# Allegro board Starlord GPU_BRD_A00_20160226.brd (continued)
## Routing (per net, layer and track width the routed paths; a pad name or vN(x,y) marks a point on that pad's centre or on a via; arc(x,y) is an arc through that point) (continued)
FBA_CMD27: length 37.3
  TOP w0.114: v1(33.92,67.36) 33.92,66.9 v2(34.02,66.8) ; v2(21.45,85.27) 21.53,85.27 VRAM3.H5
  L3 w0.127: v2(21.45,85.27) 20.92,85.81 20.92,88.55 20.77,88.7 20.28,88.7 20.14,88.55 20.14,78.59 23.37,75.35 23.37,74.47 26.39,71.45 30.41,71.45 31.4,70.47 31.69,70.47 32.11,70.06 32.11,68.98 32.92,68.17 32.95,68.16 33.23,68.16 33.82,67.57 33.82,67 v2(34.02,66.8)
  BOTTOM w0.114: VRAM3.H5 21.53,85.27 v2(21.45,85.27) ; v2(34.02,66.8) GPU1.J24
FBA_CMD28: length 36.3
  TOP w0.114: v2(24,83.6) 24,83.6 23.61,84 VRAM3.G3
  L3 w0.127: v2(32.48,72.14) 32.48,72.18 27.75,76.9 27.75,80.98 27.42,81.31 26.42,81.31 26.25,81.47 26.25,81.8 26.42,81.97 28.2,81.97 28.36,82.13 28.36,82.46 28.2,82.63 26.42,82.63 26.25,82.79 26.25,83.12 26.42,83.29 28.2,83.29 28.36,83.45 28.36,83.78 28.2,83.95 26.42,83.95 26.25,84.11 26.25,84.44 26.42,84.61 28.2,84.61 28.36,84.77 28.36,85.12 28.22,85.27 25.78,85.27 25.25,84.74 25.25,83.86 24.99,83.6 v2(24,83.6)
  BOTTOM w0.114: GPU1.K27 33.62,69.62 33.5,69.74 33.5,70.9 32.48,71.92 v2(32.48,72.14) ; VRAM3.G3 v2(24,83.6)
FBA_CMD29: length 39.4
  TOP w0.114: v2(23.99,85.99) 24.38,85.6 VRAM3.J2
  L3 w0.127: v2(34.1,72.19) 34.1,72.35 29.62,76.84 29.62,89.82 29.32,90.12 27.36,90.12 27.2,90.28 27.2,91.89 27.03,92.05 26.7,92.05 26.54,91.89 26.54,90.28 26.37,90.12 25.08,90.12 24.86,89.89 24.86,87.76 24.5,87.4 24.5,86.51 v2(23.99,85.99)
  BOTTOM w0.114: VRAM3.J2 24.38,85.6 v2(23.99,85.99) ; R7521.2 34.14,72.15 v2(34.1,72.19) 34.1,72.09 33.74,71.73 33.74,69.84 33.97,69.61 33.97,67.84 33.62,67.49 GPU1.K25
FBA_CMD30: length 43.3
  TOP w0.114: R7524.1 v1(27.63,85.86) 26.46,85.86 25.8,85.19 v2(23.99,85.19) 23.99,85.21 VRAM3.J3
  L3 w0.127: v2(34.15,71.45) 33.36,72.25 33.36,72.51 29.2,76.66 29.2,89.36 29.07,89.49 28.67,89.49 28.54,89.36 28.54,87.95 28.41,87.82 28.01,87.82 27.88,87.95 27.88,89.31 27.75,89.44 27.35,89.44 27.22,89.31 27.22,87.95 27.09,87.82 26.56,87.82 26.39,87.99 26.39,89.07 26.22,89.24 25.45,89.24 25.24,89.03 25.24,85.82 24.97,85.55 24.35,85.55 v2(23.99,85.19)
  BOTTOM w0.114: GPU1.J27 34.42,69.5 33.98,69.94 33.98,71.28 v2(34.15,71.45) ; VRAM3.J3 23.99,85.21 v2(23.99,85.19)
FBA_CMD31: length 38.9
  TOP w0.114: v2(23.2,86.8) 23.2,86.8 VRAM3.L3
  L3 w0.127: v2(23.2,86.8) 23.2,87.5 23.49,87.79 24.32,87.79 24.45,87.91 24.45,92.18 24.81,92.54 27.82,92.54 30.04,90.33 30.04,77.01 34.59,72.46 34.59,71.24 34.55,71.19 v2(34.55,70.84)
  BOTTOM w0.114: v2(34.55,70.84) 34.22,70.51 34.22,70.04 34.68,69.58 34.68,69.03 34.77,68.94 34.77,68.66 34.42,68.31 GPU1.J26 ; VRAM3.L3 23.6,87.2 v2(23.2,86.8)
FBA_D0: length 24.9
  L6 w0.127: v2(39.64,78.74) 39.64,77.97 44.08,73.53 44.08,65.33 42.23,63.48 41.47,63.48 39.51,61.52 38.01,61.52 37.49,60.99 v2(37.42,60.99)
  BOTTOM w0.114: GPU1.E18 37.43,61.05 37.43,61 v2(37.42,60.99) ; v2(39.64,78.74) 39.64,78.76 VRAM1.A4
FBA_D1: length 25.8
  L6 w0.127: v2(36.57,60.99) 36.59,60.99 37.44,61.84 39.39,61.84 41.35,63.8 41.78,63.8 43.73,65.74 43.73,73.13 v2(38.78,78.08)
  BOTTOM w0.114: GPU1.F18 36.59,61.05 36.59,61.01 v2(36.57,60.99) ; VRAM1.A2 37.6,79.11 38.63,78.08 v2(38.78,78.08)
FBA_D2: length 28.5
  TOP w0.114: v2(37.38,59.34) 36.99,59.72 v1(36.99,59.77)
  L6 w0.127: v2(37.38,59.34) 37.49,59.45 39.45,59.45 44.8,64.79 44.8,74.54 39.92,79.42 39.78,79.42 v2(39.6,79.6)
  BOTTOM w0.114: v2(39.6,79.6) VRAM1.B4 ; GPU1.E16 37.79,59.74 37.38,59.34 v2(37.38,59.34)
FBA_D3: length 30.2
  L6 w0.127: v2(36.57,60.18) 36.99,59.76 37.83,59.76 37.88,59.71 39.18,59.71 44.44,64.98 44.44,73.76 40.19,78.01 40.19,78.79 39.81,79.16 39.25,79.16 v2(38.8,78.72)
  BOTTOM w0.114: v2(36.57,60.18) 36.96,60.57 GPU1.F17 ; v2(38.8,78.72) 38.33,78.72 37.99,79.06 37.99,79.61 VRAM1.B2
FBA_D4: length 27.8
  TOP w0.114: v2(39,63.45) 39.48,63.45 v1(39.55,63.38)
  L6 w0.127: v2(39,63.45) 39.49,63.45 40.9,64.86 41.37,64.86 42.55,66.04 42.55,70.79 39.08,74.26 39.08,75.2 36.81,77.47 36.81,81.01 36.78,81.04 36.78,81.39 38.61,83.22 38.97,83.22 39.39,82.81 v2(39.6,82.81)
  BOTTOM w0.114: VRAM1.E4 39.2,82.4 v2(39.6,82.81) ; GPU1.D20 38.99,63.45 v2(39,63.45)
FBA_D5: length 26.5
  L6 w0.127: v2(37.2,82.81) 36.73,82.81 36.44,83.1 36.09,83.1 35.82,82.83 35.82,77.65 38.54,74.92 38.54,69.85 41.44,66.95 41.44,65.54 41.17,65.26 40.75,65.26 39.36,63.87 38.61,63.87 v2(38.19,63.46)
  BOTTOM w0.114: v2(38.19,63.46) 38.19,63.5 GPU1.D21 ; VRAM1.E2 37.2,82.8 v2(37.2,82.81)
FBA_D6: length 31.5
  TOP w0.114: v1(36.55,62.03) 36.55,62.65 v2(36.55,62.66)
  L6 w0.127: v2(39.6,83.61) 39.35,83.85 36.6,83.85 36.44,84.01 36.09,84.01 35.11,83.03 35.11,76.98 37.4,74.69 37.4,69.93 40.23,67.1 40.23,65.74 39.18,64.69 38.36,64.69 37.57,63.9 37.21,63.9 36.92,63.61 36.92,63.02 v2(36.55,62.66)
  BOTTOM w0.114: VRAM1.F4 39.2,83.21 v2(39.6,83.61) ; v2(36.55,62.66) 36.56,62.66 GPU1.F20
FBA_D7: length 27.4
  TOP w0.114: v1(36.74,63.3) 37.2,63.3 v2(37.38,63.48)
  L6 w0.127: v2(37.38,63.48) 37.51,63.48 38.16,64.12 39.11,64.12 40.58,65.6 40.58,67.3 37.97,69.91 37.97,74.83 35.46,77.34 35.46,82.83 36.22,83.59 v2(36.26,83.59)
  BOTTOM w0.114: VRAM1.F2 37.21,83.59 v2(36.26,83.59) ; GPU1.E21 37.42,63.52 v2(37.38,63.48)
FBA_D8: length 29.8
  TOP w0.114: VRAM2.U11 44.38,78.78 v2(44.38,78.74)
  L6 w0.127: v2(38.18,58.51) 38.38,58.51 38.78,58.11 39.23,58.11 39.62,58.51 39.93,58.51 40.15,58.73 41.06,58.73 47.41,65.08 47.41,68.5 46.55,69.36 46.55,77.07 46.92,77.44 46.92,78 46.61,78.3 44.82,78.3 v2(44.38,78.74)
  BOTTOM w0.114: v2(38.18,58.51) 38.18,58.56 GPU1.E15
FBA_D9: length 30.1
  TOP w0.114: v2(46.5,77.82) 46.5,78.48 46.4,78.59 VRAM2.U13 ; v1(38.65,59.01) 38.65,58.86 v2(38.98,58.53)
  L6 w0.127: v2(38.98,58.53) 39.28,58.53 39.51,58.76 39.83,58.76 40.32,59.26 41.17,59.26 42.29,60.39 42.29,60.47 46.2,64.37 46.2,65.43 46.32,65.55 46.93,65.55 47.06,65.68 47.06,65.93 46.93,66.06 46.32,66.06 46.2,66.19 46.2,66.44 46.32,66.57 46.93,66.57 47.06,66.7 47.06,66.95 46.93,67.08 46.32,67.08 46.2,67.2 46.2,67.46 46.32,67.59 46.93,67.59 47.06,67.71 47.06,67.97 46.93,68.09 46.32,68.09 46.2,68.22 46.2,77.52 v2(46.5,77.82)
  BOTTOM w0.114: v2(38.98,58.53) 38.98,58.56 GPU1.D15
FBA_D10: length 31.2
  TOP w0.114: v2(44.4,79.6) 44.8,80 VRAM2.T11
  L6 w0.127: v2(37.38,58.5) 37.53,58.5 38.05,59.02 39.71,59.02 40.38,59.69 41.24,59.69 42.04,60.49 42.04,60.79 45.84,64.59 45.84,76.5 45.66,76.68 45.48,76.68 45.04,76.24 44.86,76.24 44.68,76.42 44.68,76.6 45.12,77.04 45.12,77.22 44.94,77.4 44.76,77.4 44.32,76.96 44.14,76.96 43.96,77.14 43.96,77.32 44.4,77.76 44.4,77.94 43.96,78.38 43.96,79.16 v2(44.4,79.6)
  BOTTOM w0.114: GPU1.F15 37.38,58.52 v2(37.38,58.5)
FBA_D11: length 35
  TOP w0.114: v2(47.74,78.18) 47.74,78.18 47.7,78.18 46.79,79.09 46.79,79.61 VRAM2.T13
  L6 w0.127: v2(47.74,78.18) 47.74,77.76 47.06,77.07 47.06,73.18 47.78,72.45 47.78,72.21 47.66,72.08 47.11,72.08 46.98,71.95 46.98,71.7 47.11,71.57 47.66,71.57 47.78,71.44 47.78,71.19 47.66,71.06 47.11,71.06 46.98,70.94 46.98,70.68 47.11,70.56 47.66,70.56 47.78,70.43 47.78,70.17 47.66,70.05 47.11,70.05 46.98,69.92 46.98,69.67 47.11,69.54 47.66,69.54 47.78,69.41 47.78,64.95 42.8,59.97 42.8,59.97 41.31,58.47 40.26,58.47 40.04,58.25 39.75,58.25 39.35,57.86 38.62,57.86 38.39,58.08 38.04,58.08 37.78,57.83 37.78,57.51 37.36,57.09 v2(37.36,56.85)
  BOTTOM w0.114: v2(37.36,56.85) 37.36,56.86 GPU1.F13
FBA_D12: length 36.4
  TOP w0.114: v2(45.2,82.81) 44.8,82.41 VRAM2.N11
  L6 w0.127: v2(39.81,56.86) 40.24,56.43 41.59,56.43 42.42,57.25 42.42,57.46 49.28,64.33 49.28,81.17 48.92,81.54 48.92,82.48 48.68,82.73 45.28,82.73 v2(45.2,82.81)
  BOTTOM w0.114: GPU1.C13 39.41,57.26 v2(39.81,56.86)
FBA_D13: length 32.1
  TOP w0.114: v1(40.25,57.31) 40.59,56.97 v2(40.59,56.86) ; v2(46.8,81.99) 46.8,82 VRAM2.N13
  L6 w0.127: v2(40.59,56.86) 40.81,56.86 41.4,57.45 41.89,57.45 48.93,64.48 48.93,80.72 48,81.65 47.15,81.65 v2(46.8,81.99)
  BOTTOM w0.114: v2(40.59,56.86) 40.55,56.9 40.55,56.91 GPU1.B13
FBA_D14: length 41.9
  TOP w0.114: v2(44.4,83.6) 44.8,83.2 VRAM2.M11
  L6 w0.127: v2(38.2,56.86) 38.41,56.86 38.83,56.43 39.18,56.43 39.69,55.92 41.86,55.92 42.55,56.61 43.32,56.61 44.07,57.37 44.07,58.05 49.99,63.97 49.99,82.31 48.23,84.07 44.88,84.07 v2(44.4,83.6)
  BOTTOM w0.114: v2(38.2,56.86) 37.8,57.25 GPU1.E13
FBA_D15: length 37.6
  TOP w0.114: VRAM2.M13 46.4,83.2 v2(46.8,83.6) ; v2(39,56.85) 38.78,57.08 v1(38.78,57.38)
  L6 w0.127: v2(39,56.85) 39.17,56.69 39.28,56.69 39.79,56.18 41.7,56.18 49.64,64.12 49.64,82.16 47.98,83.82 47.02,83.82 v2(46.8,83.6)
  BOTTOM w0.114: v2(39,56.85) 39,56.86 GPU1.D13
FBA_D16: length 46.2
  BOTTOM w0.114: VRAM1.U11 44.8,92.19 44.79,92.2 44.79,92.61 45.18,93 48.36,93 49.44,91.91 49.44,91.45 51.65,89.24 v1(51.65,89.24) 51.77,89.11 51.77,68.26 42.11,58.59 40.55,58.59 GPU1.B15
FBA_D17: length 42.7
  BOTTOM w0.114: VRAM1.U13 46.92,92.52 48.01,92.52 48.76,91.77 48.76,90.9 51.09,88.57 51.09,76.89 50.46,76.26 v1(50.46,71.56) 50.47,71.55 50.47,67.92 41.94,59.39 40.06,59.39 39.71,59.74 GPU1.C16
FBA_D18: length 48.4
  BOTTOM w0.114: GPU1.A13 41.26,57.26 52.39,68.38 v1(52.39,85.83) 52.39,86.23 52.12,86.5 52.12,89.72 49.79,92.05 49.79,92.06 48.6,93.24 45.08,93.24 44.46,92.62 44.46,91.54 VRAM1.T11
FBA_D19: length 43.5
  BOTTOM w0.114: GPU1.A15 41.97,58.94 50.97,67.93 v1(50.97,75.62) 51.43,76.08 51.43,88.71 49.1,91.04 49.1,91.77 48.11,92.76 46.65,92.76 46.04,92.15 46.04,91.56 VRAM1.T13
FBA_D20: length 38
  BOTTOM w0.114: GPU1.B18 40.51,61.42 40.86,61.07 41.14,61.07 41.24,61.16 42.15,61.16 48.94,67.95 v1(48.94,70.79) 48.94,76.73 49.98,77.78 49.98,87.67 48.33,89.32 47.99,89.32 47.92,89.25 47.73,89.25 47.7,89.21 45.4,89.21 44.99,88.8 VRAM1.N11
FBA_D21: length 33.9
  BOTTOM w0.114: VRAM1.N13 46.52,88.8 46.89,88.44 47.95,88.44 48,88.49 48.37,88.49 48.83,88.03 48.83,86.89 49.64,86.08 49.64,77.92 48.3,76.58 v1(48.3,72.83) 48.3,67.8 41.92,61.42 GPU1.A18
FBA_D22: length 32.7
  BOTTOM w0.114: VRAM1.M11 45.22,87.58 46.53,87.58 46.84,87.27 46.84,87.05 47.13,86.76 47.35,86.76 47.57,86.54 48.2,86.54 48.74,86 48.74,85.3 48.42,84.98 48.42,84.06 48.91,83.57 48.91,78.39 46.65,76.13 v1(46.65,72.83) 46.65,67.12 41.75,62.22 GPU1.A19
FBA_D23: length 33.5
  BOTTOM w0.114: VRAM1.M13 46.69,88 47.13,87.56 47.72,87.56 48.72,86.56 48.72,86.52 49.3,85.94 49.3,78.16 47.41,76.27 v1(47.41,71.81) 47.41,67.4 41.89,61.87 39.75,61.87 GPU1.C19
FBA_D24: length 39.7
  TOP w0.114: VRAM2.A4 39.2,92.86 38.55,93.51 37.53,93.51 37.25,93.23 35.44,93.23 v2(35.4,93.27)
  BOTTOM w0.114: GPU1.B24 40.59,66.79 41.37,66.79 42.35,67.78 42.35,69.46 39.67,72.14 37.95,72.14 32.68,77.41 32.68,83.74 32.34,84.08 32.34,90.21 v1(33.62,91.49) v2(35.4,93.27)
FBA_D25: length 38.2
  TOP w0.114: VRAM2.A2 37.6,92.01 v2(37.18,92.43)
  BOTTOM w0.114: GPU1.C23 39.55,65.55 39.9,65.2 40.63,65.2 40.72,65.29 41.15,65.29 42.83,66.97 42.83,69.94 39.95,72.83 38.37,72.83 33.36,77.83 33.36,84.06 33.1,84.33 v1(33.1,88.92) 33.1,89.73 34.98,91.61 34.98,91.69 36.14,92.85 36.76,92.85 v2(37.18,92.43)
FBA_D26: length 39.9
  TOP w0.114: v2(39.6,91.6) 39.2,91.2 VRAM2.B4
  BOTTOM w0.114: v2(39.6,91.6) 39.6,92.2 38.11,93.68 35.23,93.68 31.99,90.45 31.99,83.94 32.33,83.61 32.33,83.03 32.25,82.94 v1(32.25,82.13) 32.25,77.36 37.81,71.8 39.53,71.8 40.08,71.24 42.11,69.21 42.11,67.88 41.43,67.2 GPU1.A25
FBA_D27: length 38
  TOP w0.114: v2(37.71,93.07) 37.99,92.79 37.99,91.54 37.64,91.2 VRAM2.B2
  BOTTOM w0.114: GPU1.A24 41.06,66.46 41.38,66.46 42.59,67.68 42.59,69.7 39.81,72.48 38.21,72.48 33.02,77.67 33.02,83.89 32.68,84.23 32.68,89.97 v1(32.92,90.21) 35.8,93.09 37.69,93.09 v2(37.71,93.07)
FBA_D28: length 37.3
  TOP w0.114: v2(39.6,89.21) 39.2,88.81 VRAM2.E4
  BOTTOM w0.114: v2(39.6,89.21) 39.12,89.21 38.86,89.46 38.86,89.65 38.55,89.96 36.42,89.96 36.28,90.1 35.73,90.1 v1(34.66,89.03) 34.47,88.84 34.47,87.64 34.32,87.49 34.32,84.79 34.47,84.64 34.47,78.67 39.21,73.93 40.41,73.93 43.56,70.78 43.56,66.42 41.24,64.11 41.21,64.11 GPU1.A21
FBA_D29: length 34.8
  TOP w0.114: v2(37.2,89.2) VRAM2.E2
  BOTTOM w0.114: v2(37.2,89.2) 37.19,89.21 35.94,89.21 34.81,88.09 34.81,87.5 34.66,87.35 34.66,84.93 34.81,84.78 34.81,78.82 39.19,74.44 v1(39.64,74.44) 40.39,74.44 43.97,70.85 43.97,66.38 41.14,63.55 40.86,63.55 40.51,63.9 GPU1.B21
FBA_D30: length 37.1
  TOP w0.114: VRAM2.F4 39.2,88 v2(38.8,87.6)
  BOTTOM w0.114: GPU1.C20 39.71,63.06 40.2,62.57 41.14,62.57 41.16,62.56 41.75,62.56 42.15,62.96 42.15,63.53 44.66,66.04 44.66,71.28 v1(42.86,73.08) 40.46,75.48 39.12,75.48 35.5,79.1 35.5,85.22 35.3,85.42 35.3,86.87 36.05,87.63 38.78,87.63 v2(38.8,87.6)
FBA_D31: length 35.7
  TOP w0.114: v2(37.21,88.4) 37.6,88.01 VRAM2.F2
  BOTTOM w0.114: GPU1.C21 39.71,63.9 40.06,63.55 40.51,63.55 40.76,63.31 41.24,63.31 41.34,63.41 41.49,63.41 44.31,66.23 44.31,71.11 v1(41.5,73.92) 40.52,74.91 39.21,74.91 35.16,78.96 35.16,84.92 35,85.07 35,87.2 35.19,87.39 35.19,88.12 35.51,88.45 35.89,88.45 35.95,88.39 37.19,88.39 v2(37.21,88.4)
FBA_D32: length 18.4
  TOP w0.114: v2(22.38,78.74) 22.38,78.78 VRAM3.A4
  L6 w0.127: v2(29.05,64.36) 29.05,64.37 29.07,64.39 29.07,65.16 28.93,65.3 28.93,67.11 28.56,67.48 28.56,70.29 22.38,76.47 v2(22.38,78.74)
  BOTTOM w0.114: v2(29.05,64.36) 29.45,64.76 GPU1.R22
FBA_D33: length 16.7
  TOP w0.114: v2(29.89,65.98) 30.28,66.37 v1(30.32,66.37) ; v2(24.55,78.57) 24.4,78.72 VRAM3.A2
  L6 w0.127: v2(24.55,78.57) 24.95,78.17 24.95,75.04 29.07,70.91 29.07,67.69 29.45,67.31 29.45,66.42 v2(29.89,65.98)
  BOTTOM w0.114: v2(29.89,65.98) 29.88,65.98 GPU1.R24
FBA_D34: length 19.5
  TOP w0.114: VRAM3.B4 22.8,80 22.39,79.6 v2(22.39,79.58)
  L6 w0.127: v2(28.23,64.37) 28.23,64.38 28.67,64.81 28.67,66.64 28.67,66.65 28.67,67.01 27.56,68.12 27.56,70.78 21.96,76.38 21.96,79.16 22.38,79.58 v2(22.39,79.58)
  BOTTOM w0.114: GPU1.T22 28.62,64.76 28.23,64.38 v2(28.23,64.37)
FBA_D35: length 18
  TOP w0.114: VRAM3.B2 24.6,79.8 24.6,79.75 24.84,79.51 24.84,79.05 24.96,78.92 24.96,78.37 v2(24.52,77.93)
  L6 w0.127: v2(29.84,65.19) 29.19,65.85 29.19,67.22 28.82,67.58 28.82,70.6 24.52,74.9 v2(24.52,77.93)
  BOTTOM w0.114: v2(29.84,65.19) 29.46,65.58 GPU1.R23
FBA_D36: length 22.5
  TOP w0.114: v2(22.39,81.99) 22.39,82.01 22.79,82.4 VRAM3.E4 ; v2(30.72,67.57) 30.92,67.37 v1(31.43,67.37)
  L6 w0.127: v2(22.39,81.99) 22.82,82.42 24.57,82.42 24.61,82.39 25.94,82.39 27.83,80.5 27.83,74.64 30.72,71.75 v2(30.72,67.57)
  BOTTOM w0.114: v2(30.72,67.57) 30.75,67.54 30.8,67.54 GPU1.N25
FBA_D37: length 18.9
  TOP w0.114: VRAM3.E2 24.74,82.06 25.65,82.06 v2(25.75,81.97) ; v1(29.8,68.87) 29.8,69.41 v2(30.17,69.78)
  L6 w0.127: v2(25.75,81.97) 25.86,81.97 27.47,80.35 27.47,74.49 30.17,71.8 v2(30.17,69.78)
  BOTTOM w0.114: GPU1.N26 30.76,68.38 30.76,69.15 30.17,69.74 v2(30.17,69.78)
FBA_D38: length 26.2
  TOP w0.114: v2(22.42,82.81) 22.42,82.82 VRAM3.F4
  L6 w0.127: v2(22.42,82.81) 23.83,82.81 25.09,84.06 25.92,84.06 28.62,81.37 28.62,74.99 31.97,71.63 31.97,67.24 v2(30.72,65.99)
  BOTTOM w0.114: GPU1.N23 31.12,65.6 30.73,65.99 v2(30.72,65.99)
FBA_D39: length 21.2
  TOP w0.114: VRAM3.F2 24.78,82.82 v2(24.78,82.81)
  L6 w0.127: v2(24.78,82.81) 25.2,83.23 25.92,83.23 28.26,80.89 28.26,74.76 31.09,71.92 31.09,67.79 31.14,67.75 31.14,67.19 v2(30.75,66.8)
  BOTTOM w0.114: v2(30.75,66.8) 31.14,66.41 GPU1.N24
FBA_D40: length 18.7
  L6 w0.127: v2(26.58,65.15) 26.71,65.28 26.71,66.27 26.74,66.3 26.74,69.24 18.36,77.62 18.36,77.88 17.83,78.41 17.83,78.55 v2(17.64,78.74)
  BOTTOM w0.114: VRAM4.U11 17.64,78.76 v2(17.64,78.74) ; GPU1.V23 26.58,65.2 v2(26.58,65.15)
FBA_D41: length 21.5
  TOP w0.114: v1(25.91,64.62) 26.31,64.62 v2(26.57,64.36)
  L6 w0.127: v2(17.59,78.06) 17.59,77.88 26.41,69.06 26.41,65.57 26.16,65.33 26.16,64.77 v2(26.57,64.36)
  BOTTOM w0.114: v2(26.57,64.36) 26.98,64.76 GPU1.V22 ; v2(17.59,78.06) 17.13,78.06 16.93,78.27 16.44,78.27 15.6,79.11 VRAM4.U13
FBA_D42: length 21.2
  TOP w0.114: v1(28.92,65.1) 28.27,65.1 v2(28.22,65.15)
  L6 w0.127: v2(28.22,65.15) 27.82,65.55 27.82,66.6 27.83,66.61 27.83,67.02 27.31,67.54 27.31,69.67 19.07,77.91 19.07,78.18 19.06,78.19 19.06,78.84 18.68,79.21 18.23,79.21 17.93,79.52 17.68,79.52 v2(17.6,79.6)
  BOTTOM w0.114: v2(28.22,65.15) 28.23,65.17 28.23,65.18 GPU1.T23 ; v2(17.6,79.6) VRAM4.T11
FBA_D43: length 22.7
  L6 w0.127: v2(27.42,64.34) 27.02,64.75 27,64.76 27,65.78 26.97,65.82 26.97,66.17 26.99,66.19 26.99,69.49 18.71,77.76 18.71,78.03 18.37,78.38 18.33,78.38 18.09,78.62 18.09,78.89 17.81,79.16 17.47,79.16 17.05,78.74 v2(16.78,78.74)
  BOTTOM w0.114: VRAM4.T13 15.99,79.61 15.99,79.06 16.33,78.72 16.75,78.72 v2(16.78,78.74) ; GPU1.U22 27.47,64.41 27.47,64.39 v2(27.42,64.34)
FBA_D44: length 24.5
  TOP w0.114: v2(24.93,66.78) 24.6,67.11 v1(24.6,67.29)
  L6 w0.127: v2(24.93,66.78) 24.73,66.78 14.81,76.7 14.81,78.97 14.78,79 14.78,81.39 16.61,83.22 17.18,83.22 v2(17.59,82.81)
  BOTTOM w0.114: v2(17.59,82.81) 17.59,82.79 VRAM4.N11 ; GPU1.Y24 24.96,66.78 24.93,66.78 v2(24.93,66.78)
FBA_D45: length 23.7
  TOP w0.114: v1(23.59,66.53) 23.82,66.53 v2(24.09,66.8)
  L6 w0.127: v2(15.2,82.81) 14.73,82.81 14.44,83.1 14.09,83.1 13.82,82.83 13.82,77.15 24.09,66.88 v2(24.09,66.8)
  BOTTOM w0.114: v2(15.2,82.81) 15.2,82.8 VRAM4.N13 ; v2(24.09,66.8) 24.1,66.8 GPU1.AA24
FBA_D46: length 30.8
  L6 w0.127: v2(25.75,65.21) 25.21,64.67 24.47,64.67 23.42,65.72 23.42,66.46 13.05,76.84 13.05,82.96 14.02,83.94 14.91,83.94 15.24,83.61 v2(17.6,83.61)
  BOTTOM w0.114: v2(17.6,83.61) 17.2,83.21 VRAM4.M11 ; v2(25.75,65.21) 25.75,65.17 GPU1.Y22
FBA_D47: length 26.8
  TOP w0.114: v2(24.91,65.13) 24.77,65.28 v1(24.22,65.28)
  L6 w0.127: v2(24.91,65.13) 24.47,65.58 23.92,65.58 23.68,65.82 23.68,66.71 13.46,76.93 13.46,82.83 14.15,83.52 v2(14.26,83.52)
  BOTTOM w0.114: VRAM4.M13 15.21,83.59 14.34,83.59 v2(14.26,83.52) ; v2(24.91,65.13) 24.5,65.55 GPU1.AA23
FBA_D48: length 36.7
  TOP w0.114: VRAM3.U11 17.2,92.59 16.31,93.48 15.36,93.48 15.15,93.27 v2(13.4,93.27)
  BOTTOM w0.114: v2(13.4,93.27) 12.87,93.27 v1(12.49,92.89) 10.56,90.97 10.56,83.23 10.68,83.12 10.68,78.22 14.21,74.69 16.18,74.69 22,68.87 GPU1.AD27
FBA_D49: length 35.5
  TOP w0.114: v2(15.18,92.43) 15.6,92.01 VRAM3.U13
  BOTTOM w0.114: v2(15.18,92.43) 14.76,92.85 14.22,92.85 12.1,90.73 11.98,90.73 v1(11.47,90.22) 11.25,90 11.25,83.51 11.36,83.4 11.36,78.5 14.49,75.38 17.33,75.38 23.11,69.59 23.11,69.25 23.11,68.27 23.35,68.03 23.35,67.86 23.7,67.51 GPU1.AB25
FBA_D50: length 40.1
  TOP w0.114: v2(17.6,91.6) 17.2,91.2 VRAM3.T11
  BOTTOM w0.114: GPU1.AD26 22,68.14 21.65,68.49 21.65,68.88 19.91,70.62 19.53,70.62 15.8,74.35 14.06,74.35 10.34,78.08 10.34,82.97 10.22,83.09 10.22,91.52 12.87,94.16 15.63,94.16 ; v2(17.6,91.6) 17.6,92.2 15.63,94.16 ; 15.63,94.16 v1(15.66,94.16)
FBA_D51: length 37.4
  TOP w0.114: VRAM3.T13 15.96,91.56 15.96,92.82 v2(15.71,93.07)
  BOTTOM w0.114: GPU1.AC25 22.85,67.36 22.35,67.86 22.35,69.06 16.37,75.03 14.35,75.03 11.02,78.36 11.02,83.26 10.91,83.37 10.91,90.42 v1(12.11,91.62) 12.6,92.12 13,92.12 13.97,93.09 15.69,93.09 v2(15.71,93.07)
FBA_D52: length 33.6
  TOP w0.114: v2(16.79,89.2) 17.18,88.81 17.19,88.81 VRAM3.N11
  BOTTOM w0.114: v2(16.79,89.2) 16.79,89.72 16.55,89.96 13.3,89.96 12.36,89.02 12.36,83.97 12.47,83.86 12.47,78.96 14.95,76.48 18.86,76.48 v1(21.79,73.56) 24.37,70.98 24.37,68.93 GPU1.AA27
FBA_D53: length 31.1
  TOP w0.114: v2(15.2,89.2) VRAM3.N13
  BOTTOM w0.114: v2(15.2,89.2) 14.91,89.2 14.9,89.19 14.05,89.19 12.7,87.83 12.7,84.12 12.81,84 12.81,79.1 15.09,76.83 19,76.83 21.71,74.12 21.99,74.12 v1(23.66,72.44) 24.72,71.39 24.72,69.12 24.85,68.99 24.85,68.66 24.5,68.31 GPU1.AA26
FBA_D54: length 32.2
  TOP w0.114: v2(16.8,87.61) 17.2,88 VRAM3.M11
  BOTTOM w0.114: GPU1.W26 26.18,68.05 25.83,68.4 25.83,72.18 v1(23.79,74.22) 22.9,75.11 21.69,75.11 19.39,77.41 15.19,77.41 13.82,78.78 13.82,85.65 13.18,86.3 13.18,87.31 13.42,87.55 13.95,87.55 14.03,87.63 16.56,87.63 16.58,87.61 v2(16.8,87.61)
FBA_D55: length 31.7
  TOP w0.114: v2(15.21,88.4) 15.6,88.01 VRAM3.M13
  BOTTOM w0.114: v2(15.21,88.4) 14.53,88.4 14.47,88.34 14.25,88.33 14.01,88.33 13.97,88.37 13.58,88.37 12.94,87.73 12.94,86.17 13.56,85.55 13.56,78.7 15.09,77.17 19.15,77.17 21.59,74.73 22.27,74.73 v1(24.93,72.06) 24.96,72.04 24.96,69.22 25.09,69.09 25.09,68.56 24.99,68.46 24.99,67.55 GPU1.Y25
FBA_D56: length 31.1
  BOTTOM w0.114: VRAM4.A4 22.8,92.19 22.79,92.2 22.79,92.61 23.18,93 26.36,93 27.35,92.01 27.72,92.01 v1(28.11,91.62) 29.69,90.03 29.69,69.42 29.81,69.3 29.81,68.35 GPU1.R26
FBA_D57: length 28.5
  BOTTOM w0.114: GPU1.T25 29.01,67.55 29.01,88.69 v1(28.87,88.83) 28.87,89.34 26.76,91.45 26.76,91.77 26.01,92.52 24.92,92.52 VRAM4.A2
FBA_D58: length 32.8
  BOTTOM w0.114: GPU1.N27 31.14,69.39 30.05,70.47 30.05,90.35 29.77,90.63 29.77,90.97 v1(27.5,93.24) 23.08,93.24 22.46,92.62 22.46,91.54 VRAM4.B4
FBA_D59: length 28.8
  BOTTOM w0.114: VRAM4.B2 24.04,91.56 24.04,92.15 24.65,92.76 26.12,92.76 28.51,90.37 v1(28.51,90.35) 29.35,89.5 29.35,69.42 29.46,69.31 GPU1.R27
FBA_D60: length 25.7
  BOTTOM w0.114: GPU1.V26 27.13,68.15 27.13,68.46 27.33,68.66 27.33,69.54 27.85,70.07 v1(27.85,84.76) 27.85,84.89 27.34,85.4 27.34,87.83 25.96,89.21 23.21,89.21 VRAM4.E4
FBA_D61: length 22.1
  BOTTOM w0.114: GPU1.V27 26.98,69.53 27.47,70.03 v1(27.47,83.24) 27.47,84.13 27,84.6 27,87.29 25.93,88.36 25.56,88.36 25.52,88.4 24.8,88.4 VRAM4.E2
FBA_D62: length 21.8
  BOTTOM w0.114: VRAM4.F4 23.22,87.58 24.53,87.58 24.84,87.27 24.84,87.05 25.13,86.76 25.35,86.76 25.64,86.47 26.01,86.47 26.32,86.17 v1(26.32,75.62) 26.32,68.94 GPU1.W27
FBA_D63: length 23
  BOTTOM w0.114: VRAM4.F2 24.69,88 25.07,87.62 25.47,87.62 25.61,87.47 25.93,87.47 26.66,86.74 26.66,77.19 v1(26.96,76.89) 27.13,76.72 27.13,71.41 27.22,71.32 27.22,70.11 26.74,69.63 26.74,69.05 26.63,68.94 26.63,67.96 26.18,67.51 GPU1.W25
FBA_DEBUG0: length 1.6
  TOP w0.102: R7501.1 35.79,63.62 v2(36.49,64.32)
  BOTTOM w0.102: v2(36.49,64.32) 36.52,64.32 GPU1.F22
FBA_DEBUG1: length 1.3
  TOP w0.102: v2(34.89,64.32) 34.89,63.69 R7503.1
  BOTTOM w0.102: v2(34.89,64.32) 34.85,64.36 34.82,64.36 GPU1.J22
FBA_DQM0: length 24.1
  L6 w0.127: v2(39.01,62.63) 39.31,62.63 41.18,64.5 41.49,64.5 42.93,65.93 42.93,71 39.69,74.23 39.69,75.44 37.2,77.94 v2(37.2,81.21)
  BOTTOM w0.114: VRAM1.D2 37.58,81.6 v2(37.2,81.21) ; v2(39.01,62.63) 39.01,62.63 GPU1.D19
FBA_DQM1: length 33.5
  TOP w0.114: v1(37.76,58.09) 37.79,58.09 v2(38.21,57.67) ; VRAM2.P13 46.42,81.6 v2(46.8,81.22)
  L6 w0.127: v2(46.8,81.22) 46.81,81.22 46.92,81.32 47.97,81.32 48.55,80.74 48.55,64.64 41.83,57.92 41.4,57.92 40.76,57.28 38.6,57.28 v2(38.21,57.67)
  BOTTOM w0.114: v2(38.21,57.67) 38.6,58.05 GPU1.D14
FBA_DQM2: length 38.7
  BOTTOM w0.114: VRAM1.P13 46.79,89.99 47.61,89.99 47.82,90.21 48.16,90.21 50.35,88.02 50.35,77.52 49.57,76.74 v1(49.57,72.44) 49.57,68.06 42.37,60.87 41.28,60.87 41.24,60.83 40.76,60.83 40.66,60.93 39.75,60.93 GPU1.C17
FBA_DQM3: length 36.8
  TOP w0.114: v2(35.47,90.61) 35.84,90.24 36.18,90.24 36.45,89.98 37.03,89.98 37.41,89.6 VRAM2.D2
  BOTTOM w0.114: GPU1.C22 39.75,64.35 41.14,64.35 43.32,66.52 43.32,70.5 40.26,73.56 39.06,73.56 34.1,78.52 34.1,84.43 33.95,84.59 v1(33.95,87.82) 33.95,89.08 v2(35.47,90.61)
FBA_DQM4: length 18.6
  TOP w0.114: VRAM3.D2 24.42,81.6 v2(24.8,81.22)
  L6 w0.127: v2(29.87,66.82) 30.28,67.22 30.28,67.92 29.58,68.63 29.58,69.94 29.78,70.14 29.78,71.43 27,74.21 27,79.77 25.92,80.85 25.59,80.85 25.22,81.22 v2(24.8,81.22)
  BOTTOM w0.114: GPU1.P24 30.29,66.4 v2(29.87,66.82)
FBA_DQM5: length 20.6
  TOP w0.114: v2(25.74,66.79) 25.87,66.93 v1(25.87,67.41)
  L6 w0.127: v2(15.2,81.21) 15.2,78.12 25.74,67.58 v2(25.74,66.79)
  BOTTOM w0.114: GPU1.W24 26.13,66.4 v2(25.74,66.79) ; v2(15.2,81.21) 15.58,81.6 VRAM4.P13
FBA_DQM6: length 33.9
  TOP w0.114: VRAM3.P13 15.22,89.98 14.23,89.98 13.6,90.61 v2(13.47,90.61)
  BOTTOM w0.114: v2(13.47,90.61) 13.42,90.61 11.99,89.17 11.99,83.82 12.1,83.71 12.1,78.81 14.8,76.11 18.34,76.11 v1(23.41,71.05) 24.05,70.41 24.05,67.94 24.5,67.49 GPU1.AA25
FBA_DQM7: length 26.1
  BOTTOM w0.114: VRAM4.D2 24.79,89.99 25.55,89.99 25.64,90.09 26.02,90.09 27.71,88.4 27.71,86.72 v1(28.27,86.16) 28.27,70.14 27.57,69.44 27.57,68.56 27.47,68.46 27.47,67.55 GPU1.U25
FBA_EDC0: length 29.4
  TOP w0.114: v2(37.38,62.64) 37.76,62.26 v1(37.76,62.13)
  L6 w0.127: v2(38.8,77.45) 41.02,75.23 41.02,75.05 40.59,74.62 40.59,74.44 40.77,74.26 40.95,74.26 41.38,74.69 41.56,74.69 41.74,74.51 41.74,74.33 41.31,73.9 41.31,73.72 41.49,73.54 41.67,73.54 42.1,73.97 42.28,73.97 43.35,72.9 43.35,65.8 41.65,64.11 41.27,64.11 39.37,62.21 37.82,62.21 v2(37.38,62.64)
  BOTTOM w0.114: GPU1.E19 37.8,62.22 v2(37.38,62.64) ; v2(38.8,77.45) 37.24,79.01 37.24,80.44 VRAM1.C2
FBA_EDC1: length 34.1
  TOP w0.114: v2(47.77,80.27) 47.76,80.27 47.62,80.41 46.79,80.41 VRAM2.R13
  L6 w0.127: v2(47.77,80.27) 47.77,80.26 48.16,79.86 48.16,76.69 48.04,76.56 47.56,76.56 47.44,76.43 47.44,76.18 47.56,76.05 48.04,76.05 48.16,75.92 48.16,75.67 48.04,75.54 47.56,75.54 47.44,75.42 47.44,75.16 47.56,75.04 48.04,75.04 48.16,74.91 48.16,74.65 48.04,74.53 47.56,74.53 47.44,74.4 47.44,74.15 47.56,74.02 48.04,74.02 48.16,73.89 48.16,73.64 48.04,73.51 47.79,73.51 47.67,73.38 47.67,73.13 47.79,73 48.04,73 48.16,72.88 48.16,64.79 41.55,58.17 40.44,58.17 39.97,57.7 v2(39.81,57.7)
  BOTTOM w0.114: v2(39.81,57.7) 39.81,58.52 39.4,58.93 GPU1.C15
FBA_EDC2: length 39.6
  BOTTOM w0.114: GPU1.B16 40.55,60.09 41.18,60.09 41.23,60.04 42.06,60.04 50.1,68.07 v1(50.1,69.38) 50.09,69.38 50.09,76.51 50.72,77.14 50.72,88.32 47.97,91.07 47.62,91.07 47.34,90.79 46.79,90.79 VRAM1.R13
FBA_EDC3: length 36.6
  TOP w0.114: VRAM2.C2 37.46,90.4 37.06,90.8 36.65,90.8 36.36,91.09 36.1,91.09 35.68,91.52 v2(35.4,91.52)
  BOTTOM w0.114: GPU1.B22 40.39,64.89 40.65,64.89 40.82,65.05 41.25,65.05 43.07,66.87 43.07,70.22 40.1,73.19 38.91,73.19 33.73,78.37 33.73,84.21 33.48,84.47 33.48,89.52 v1(34.33,90.37) 35.4,91.44 v2(35.4,91.52)
FBA_EDC4: length 19.6
  TOP w0.114: v2(25.6,78.09) 25.93,78.41 25.93,78.99 25.38,79.53 25.37,79.53 25.27,79.64 25.05,79.64 24.84,79.85 24.84,80.36 VRAM3.C2
  L6 w0.127: v2(29.86,67.59) 29.86,67.98 29.33,68.52 29.33,71.25 25.6,74.98 25.6,75.75 25.72,75.88 26.41,75.88 26.53,76 26.53,76.26 26.41,76.38 25.72,76.38 25.6,76.51 25.6,76.77 25.72,76.89 26.41,76.89 26.53,77.02 26.53,77.27 26.41,77.4 25.72,77.4 25.6,77.53 v2(25.6,78.09)
  BOTTOM w0.114: GPU1.R25 29.47,67.2 v2(29.86,67.59)
FBA_EDC5: length 26.9
  TOP w0.114: v2(25.74,65.99) 25.98,66.22 v1(26.53,66.22)
  L6 w0.127: v2(25.74,65.99) 26.15,66.4 26.15,67.77 21.05,72.87 21.05,73.05 21.37,73.37 21.37,73.54 21.19,73.72 21.01,73.72 20.69,73.41 20.51,73.41 20.33,73.59 20.33,73.77 20.65,74.08 20.65,74.26 20.47,74.44 20.29,74.44 19.97,74.13 19.79,74.13 19.62,74.31 19.62,74.49 19.93,74.8 19.93,74.98 19.75,75.16 19.57,75.16 19.26,74.85 19.08,74.85 18.9,75.03 18.9,75.21 19.21,75.52 19.21,75.7 19.03,75.88 18.85,75.88 18.54,75.57 18.36,75.57 18.18,75.75 18.18,75.92 18.49,76.24 18.49,76.42 18.31,76.6 18.13,76.6 17.82,76.28 17.64,76.28 16.75,77.17 v2(16.75,77.85)
  BOTTOM w0.114: v2(25.74,65.99) 25.76,65.97 25.81,65.97 GPU1.W23 ; VRAM4.R13 15.24,80.44 15.24,79.01 16.42,77.83 16.73,77.83 v2(16.75,77.85)
FBA_EDC6: length 33.5
  TOP w0.114: VRAM3.R13 15.2,90.8 14.65,90.8 14.36,91.09 14.1,91.09 13.96,91.24 v2(13.48,91.24)
  BOTTOM w0.114: v2(13.48,91.24) 11.62,89.38 11.62,83.67 11.73,83.55 11.73,78.66 14.64,75.75 18.07,75.75 v1(21.76,72.06) 23.35,70.47 23.35,69.15 23.35,69.15 23.35,68.5 23.7,68.15 GPU1.AB26
FBA_EDC7: length 27.6
  BOTTOM w0.114: VRAM4.C2 24.79,90.79 25.34,90.79 25.52,90.97 25.98,90.97 26.56,90.39 26.72,90.39 26.91,90.58 27.07,90.58 27.23,90.42 27.23,90.26 27.04,90.07 27.04,89.91 27.2,89.74 27.36,89.74 27.55,89.93 27.71,89.93 27.88,89.77 27.88,89.61 27.69,89.42 27.69,89.26 28.36,88.59 v1(28.36,87.68) 28.64,87.41 28.64,69.69 28.4,69.44 28.4,69.1 28.31,69.01 28.31,68.35 GPU1.T26
FBA_MF1: length 4.1
  TOP w0.127: v2(36.19,84.76) 35.92,84.49 35.37,84.49 34.93,84.05 v1(34.41,84.05) R7811.2
  BOTTOM w0.127: VRAM1.J1 36.21,85.01 36.21,84.79 v2(36.19,84.76)
FBA_MF2: length 3.6
  TOP w0.127: VRAM2.J1 36.38,85.18 36.01,85.18 35.69,84.86 R7812.1
FBA_MF3: length 4.4
  TOP w0.127: VRAM3.J1 25.47,85.87 25.47,86.15 25.57,86.25 25.57,86.25 25.89,86.58 26.34,86.58 27.49,87.73 v1(27.57,87.73) 28.42,87.73 R7911.2
FBA_MF4: length 3.8
  TOP w0.127: R7910.1 27.32,86.77 26.88,86.33 26.23,86.33 v2(25.9,86)
  BOTTOM w0.127: VRAM4.J1 25.51,85.6 v2(25.9,86)
FBA_PLL_AVDD: length 2.6
  TOP w0.508: C7505.1 30.83,64.47 v2(30.7,64.34)
  BOTTOM w0.356: v2(30.7,64.34) 30.3,64.74 GPU1.P22 ; GPU1.H22 35.6,64.42 v2(35.6,64.29) ; GPU1.F16 36.57,59.35 v2(36.57,59.34)
  vias: v1(14.54,61.98) v3(17.06,64.29) v3(17.08,63.43) v3(18.02,64.32) v3(18.02,63.43)
FBA_SEN0: length 14
  TOP w0.127: VRAM2.J10 43.4,85.6 v2(43.37,85.63) 43.37,85.75 42.69,86.44 42.69,87.28 43.2,87.79 43.69,87.79 43.91,87.57 48.34,87.57 48.67,87.9 48.67,89.85 v1(49.6,90.78) 50.09,91.28 R7810.2
  BOTTOM w0.127: VRAM2.J10 43.4,85.6 v2(43.37,85.63)
FBA_SEN2: length 9.1
  TOP w0.127: R7909.2 12.11,86.9 12.41,87.2 v1(12.51,87.2) 12.54,87.23 13.5,87.23 v2(13.59,87.13) ; v2(18.58,85.8) 18.56,85.8 18.35,85.6 VRAM3.J10
  L6 w0.127: v2(18.58,85.8) 17.99,86.4 16.99,86.4 16.96,86.38 14.44,86.38 13.68,87.13 v2(13.59,87.13)
  BOTTOM w0.127: VRAM3.J10 18.35,85.6 18.56,85.8 v2(18.58,85.8)
FBA_VREF_FET_H: length 4.7
  TOP w0.508: R7905.2 R7902.2 9.12,81.59 v2(8.96,81.59)
  BOTTOM w0.254: v1(9.29,79.2) 8.73,79.76 Q7901.D
  BOTTOM w0.508: v2(8.96,81.59) 8.73,81.36 Q7901.D
FBA_VREF_FET_L: length 4.8
  TOP w0.508: R7804.2 51.39,91.1 v2(51.45,91.16) 51.37,91.24 R7803.2
  BOTTOM w0.254: Q7801.D 50.38,92.55 50.38,92.85 50.09,93.15 49.77,93.15 v1(49.72,93.2)
  BOTTOM w0.508: v2(51.45,91.16) 51.45,91.48 Q7801.D
FBA_VREFC0: length 9.2
  TOP w0.356: v2(47.62,85.98) 47.58,85.98 VRAM2.J14
  TOP w0.508: R7804.1 50.5,89.59 R7806.2 50.49,88.72 C7803.1 ; C7803.1 R7807.1 52.25,88.71 v1(52.31,88.65) ; C7803.1 50.26,88.71 50.25,88.73 49.62,88.73 49.24,88.34 49.24,87.59 47.99,86.35 47.98,86.35 v2(47.62,85.98)
  BOTTOM w0.356: v2(47.62,85.98) 47.58,85.98 VRAM2.J14
FBA_VREFC1: length 8
  TOP w0.33: v2(14.38,85.16) 14.8,85.57 VRAM3.J14
  TOP w0.356: v2(14.38,85.16) 14.21,84.98
  TOP w0.508: 14.21,84.98 14.21,84.52 13.09,83.4 13.08,83.4 12.44,82.76 v1(12.44,82.73) 12.41,82.73 12.31,82.63 R7904.1 C7902.1 11.55,81.72 R7903.2 11.51,80.88 R7902.1
  BOTTOM w0.356: VRAM3.J14 14.8,85.57 14.38,85.16 v2(14.38,85.16)
FBA_VREFD_H: length 34.3
  TOP w0.305: VRAM3.A10 18.1,79.2 18.5,78.79 v2(18.51,78.79)
  TOP w0.356: VRAM3.U10 18.04,92 v2(18.44,91.6)
  TOP w0.508: R7905.1 10.72,79.25 R7907.2 C7908.1 9.86,78.39 R7901.1 C7903.1 9.8,77.52 9.8,77.13 9.82,77.11 v1(9.82,76.64) 9.82,76.38 10.2,76 10.2,75.14 10.73,74.6 16.6,74.6 18.05,76.05 18.05,76.25 18.71,76.91 18.71,78.59 v2(18.51,78.79) 19.77,80.05 19.77,90.56 18.72,91.6 v2(18.44,91.6)
  BOTTOM w0.356: VRAM3.A10 18.41,78.79 v2(18.51,78.79) ; VRAM3.U10 18.04,92 v2(18.44,91.6)
FBA_VREFD_L: length 28.9
  TOP w0.356: VRAM2.U10 43.55,78.75 v2(43.45,78.75) ; v2(43.6,92.43) 43.6,92.4 VRAM2.A10
  TOP w0.508: v2(43.6,92.43) 44.57,93.4 50.19,93.4 v1(50.46,93.13) R7803.1 52.18,93.13 C7802.1 R7809.1 C7826.1 52.2,90.51 R7805.2
  BOTTOM w0.356: v2(43.6,92.43) 43.6,92.4 VRAM2.A10 ; VRAM2.U10 43.55,78.75 v2(43.45,78.75)
  BOTTOM w0.508: v2(43.45,78.75) 43.33,78.75 42.7,79.38 42.7,91.57 43.57,92.43 v2(43.6,92.43)
FBA_WCK01: length 47.9
  TOP w0.203: 41.7,62 38.69,62 38.29,61.61 38.29,61.09 v2(38.19,60.98) ; 41.7,62 v1(41.7,62.11) ; 41.7,62 42.84,62 43.78,62.95 43.78,68.04 43.41,68.41 42.13,69.69 42.13,70.58 42.53,70.98 45.37,70.98 45.58,71.18 45.58,71.59 45.37,71.79 42.53,71.79 42.13,72.19 42.13,72.87 42.53,73.26 45.33,73.26 45.53,73.47 45.53,73.87 45.33,74.08 42.53,74.08 42.13,74.47 42.13,75.15 42.53,75.55 45.37,75.55 45.58,75.75 45.58,76.16 45.37,76.36 42.53,76.36 42.13,76.76 42.13,80.22 41.55,80.81 40.64,80.81 40.24,81.21 v2(39.59,81.21) VRAM2.P4
  BOTTOM w0.203: v2(38.19,60.98) 38.19,61.01 GPU1.D18 ; VRAM2.P4 v2(39.59,81.21)
FBA_WCK01#: length 48.1
  TOP w0.203: VRAM2.P5 40.5,81.6 40.58,81.52 v2(40.59,81.52) 40.59,81.33 40.78,81.14 41.68,81.14 42.46,80.36 42.46,76.9 42.66,76.69 45.51,76.69 45.91,76.3 45.91,75.62 45.51,75.22 42.66,75.22 42.46,75.02 42.46,74.61 42.66,74.41 45.47,74.41 45.87,74.01 45.87,73.33 45.47,72.93 42.66,72.93 42.46,72.73 42.46,72.32 42.66,72.12 45.51,72.12 45.91,71.72 45.91,71.04 45.51,70.65 42.66,70.65 42.46,70.44 42.46,69.83 44.11,68.18 44.11,62.81 42.97,61.67 40.07,61.67 ; v2(38.99,60.98) 38.82,60.98 38.62,61.18 38.62,61.47 38.82,61.67 40.07,61.67 ; 40.07,61.67 v1(40.07,61.57)
  BOTTOM w0.203: GPU1.C18 39.11,61.42 38.99,61.3 v2(38.99,60.98) ; v2(40.59,81.52) 40.5,81.6 VRAM2.P5
FBA_WCK23: length 44.9
  TOP w0.203: v2(39.6,90) 39.2,89.6 VRAM2.D4
  L3 w0.127: v2(38.21,60.18) 38.46,60.18 38.83,60.55 39.84,60.55 49.99,70.7 49.99,85.32 46.19,89.12 40.28,89.12 39.76,89.64 39.76,89.84 v2(39.6,90)
  BOTTOM w0.203: v2(39.6,90) 39.2,89.6 VRAM2.D4 ; v2(38.21,60.18) 38.21,60.19 GPU1.D17
FBA_WCK23#: length 44.9
  TOP w0.203: v2(40.41,90.02) 40.38,89.99 40.38,89.98 VRAM2.D5
  L3 w0.127: v2(40.41,90.02) 40.14,90.02 40.02,89.89 40.02,89.74 40.39,89.37 46.3,89.37 50.24,85.43 50.24,70.6 39.94,60.3 39.17,60.3 v2(39,60.13)
  BOTTOM w0.203: v2(39,60.13) 38.81,60.13 38.6,59.93 GPU1.D16 ; VRAM2.D5 40.38,89.98 40.38,89.99 v2(40.41,90.02)
FBA_WCK45: length 47.5
  TOP w0.203: 23.97,68.43 21.55,68.43 20.82,69.17 20.82,71.58 21.02,71.78 25.96,71.78 26.36,72.18 26.36,72.86 25.96,73.26 21.02,73.26 20.82,73.46 20.82,73.87 21.02,74.07 25.96,74.07 26.36,74.47 26.36,75.15 25.96,75.54 21.02,75.54 20.82,75.75 20.82,80.36 21.54,81.08 21.64,81.08 21.77,81.21 v2(22.42,81.21) 22.8,81.59 VRAM3.D4 ; 23.97,68.43 v1(23.97,68.51) ; 23.97,68.43 28.64,68.43 29.41,67.66 29.41,66.4 28.97,65.97 v2(28.24,65.97)
  BOTTOM w0.203: v2(28.24,65.97) 28.66,66.39 GPU1.T24 ; VRAM3.D4 22.8,81.59 v2(22.42,81.21)
FBA_WCK45#: length 47.7
  TOP w0.203: 22.16,68.1 28.5,68.1 29.08,67.53 29.08,66.54 28.84,66.3 28.56,66.3 28.25,66.6 v2(28.25,66.79) ; 22.16,68.1 21.42,68.1 20.49,69.03 20.49,71.72 20.88,72.11 25.82,72.11 26.03,72.32 26.03,72.72 25.82,72.93 20.88,72.93 20.49,73.32 20.49,74 20.88,74.4 25.82,74.4 26.03,74.6 26.03,75.01 25.82,75.21 20.88,75.21 20.49,75.61 20.49,80.5 20.69,80.7 20.69,81.54 20.89,81.74 21.25,81.74 v2(21.45,81.54) 21.52,81.6 VRAM3.D5 ; 22.16,68.1 v1(22.16,67.97)
  BOTTOM w0.203: VRAM3.D5 21.52,81.6 v2(21.45,81.54) ; v2(28.25,66.79) 28.25,66.6 28.06,66.4 GPU1.U24
FBA_WCK67: length 43.3
  TOP w0.203: v2(22.41,89.21) 22.41,89.21 VRAM3.P4
  L3 w0.127: v2(27.39,65.99) 26.63,65.99 26.46,66.17 26.3,66.32 26.3,66.97 25.99,67.29 23.38,67.29 22.76,67.91 12.44,78.24 12.44,87.91 14.65,90.12 21.94,90.12 22.24,89.82 22.24,89.38 v2(22.41,89.21)
  BOTTOM w0.203: v2(22.41,89.21) 22.8,89.6 VRAM3.P4 ; v2(27.39,65.99) GPU1.V24
FBA_WCK67#: length 44.3
  TOP w0.203: v1(27.45,67.36) 27.45,66.82 v2(27.41,66.78) ; VRAM3.P5 22,89.45 21.74,89.18 v2(21.38,89.18)
  L3 w0.127: v2(21.38,89.18) 21.89,89.18 21.99,89.28 21.99,89.72 21.84,89.87 14.75,89.87 12.69,87.8 12.69,78.34 23.49,67.54 26.09,67.54 26.56,67.08 26.56,66.43 26.74,66.25 27.05,66.25 27.41,66.61 v2(27.41,66.78)
  BOTTOM w0.203: GPU1.V25 26.98,66.99 27.19,66.78 v2(27.41,66.78) ; v2(21.38,89.18) 21.73,89.18 22,89.45 VRAM3.P5
FBA_ZQ0: length 5
  TOP w0.254: v2(48.33,85.83) 48.43,85.83 49.54,86.94 v1(49.59,86.94) R7808.1
  BOTTOM w0.203: v2(48.33,85.83) 47.7,85.21 46.9,85.21 46.51,85.6 VRAM1.J13
FBA_ZQ1: length 4.6
  TOP w0.203: R7813.1 49.86,85.45 v1(49.5,85.45) 48.71,85.45 48.48,85.22 46.9,85.22 46.52,85.6 VRAM2.J13
FBA_ZQ2: length 4.6
  TOP w0.203: 13.46,86.02 13.47,86.01 14.62,86.01 14.63,85.99 15.1,85.99 15.5,85.6 VRAM3.J13
  TOP w0.254: R7912.1 12.28,85.19 12.36,85.27 v1(12.46,85.27) 12.46,85.36 13.12,86.02 13.46,86.02
FBA_ZQ3: length 4.7
  TOP w0.254: v2(13.67,86.5) 13.57,86.59 12.77,86.59 12.23,86.06 R7913.1
  BOTTOM w0.203: VRAM4.J13 15.56,85.6 15.17,85.99 14.53,85.99 14.28,86.24
  BOTTOM w0.254: v2(13.67,86.5) 14.03,86.5 14.28,86.24
GC6_FB_EN: length 63.4
  TOP w0.127: v2(35.02,44.68) 35.02,45.55 34.03,46.54 R7519.2
  L3 w0.127: v2(48.7,51.12) 48.05,50.47 45.9,50.47 41.9,46.48 41.9,43.44 41.52,43.06 39.97,43.06 39.25,43.78 35.92,43.78 v2(35.02,44.68) 33.76,43.42 31.24,43.42 30.58,42.76 26.62,42.76 25.85,42 23.97,42 23.44,42.54 20.78,42.54 18.93,44.39 18.93,45.61 15.98,48.56 15.98,50.99 13.32,53.65 10.55,53.65 v2(8.67,55.53)
  BOTTOM w0.127: v2(48.7,51.12) 49.86,52.28 R7623.1 v1(49.91,53.27) 49.91,54.04 D8301.1 ; v2(8.67,55.53) 8.23,55.97 GPU3.C10
GC6_FB_EN_GPU: length 12.3
  BOTTOM w0.127: v1(48.25,53.19) 48.24,53.18 R7627.1 ; GPU1.C6 39.55,51.5 40.02,51.03 42.54,51.03 43.2,50.37 44.43,50.37 44.98,50.92 47.65,50.92 48.24,51.5 R7627.1 ; R7623.2 R7627.1
GPIO5_GC6_PWR_EN: length 55.3
  TOP w0.127: PR8330.1 42.37,6.49 v2(42.53,6.33) ; v1(47.41,38.69) 46.78,38.69 v2(46.78,38.69) 45.3,40.16 42.36,40.16 40.67,41.85 40.67,46.5 39.97,47.2 R7636.2
  L6 w0.127: v2(46.78,38.69) 47.13,38.33 47.13,35.89 49.61,33.41 49.61,32.24 48.9,31.54 46.95,31.54 45.49,30.08 45.49,11.68 44.73,10.92 44.73,9.13 44.39,8.79 44.39,8.18 v2(42.53,6.33)
  BOTTOM w0.127: v2(42.53,6.33) 42.55,6.34 42.55,8.07 42.41,8.2 PQ8307.2
GPIO5_GC6_PWR_EN#: length 7.4
  TOP w0.127: v2(44.03,9.48) 43.56,9 v1(41.87,9) PR8319.1
  BOTTOM w0.127: PQ8307.5 44.57,8.2 ; 44.57,8.2 44.57,7.78 44.34,7.55 PQ8307.6 ; 44.57,8.2 44.57,9 44.08,9.48 v2(44.03,9.48)
GPIO5_GC6_PWR_EN_GPU: length 3.1
  TOP w0.127: v2(41.44,48.59) 41.44,48.7 40.53,49.61 R7633.2 39.97,49.11 R7636.1
  BOTTOM w0.127: v2(41.44,48.59) 41.42,48.61 41.42,48.62 41.04,49 GPU1.A3
GPIO5_GC6_PWR_EN_R: length 36.8
  TOP w0.127: R8306.2 41.15,7.93 C8309.1 PR8330.2 41.48,6.77 41.71,6.54 41.71,6.52 v2(41.9,6.33) ; v1(49.16,33.84) v2(49.16,33.23)
  L6 w0.127: v2(41.9,6.33) 44.14,8.56 44.14,8.89 44.48,9.24 44.48,11.02 45.24,11.78 45.24,30.19 46.84,31.79 48.8,31.79 49.16,32.16 v2(49.16,33.23)
  BOTTOM w0.127: U8301.3 48.83,33.56 v2(49.16,33.23)
GPIO9_ALERT: length 13.8
  L3 w0.127: v2(34.66,46.84) 34.7,46.88 34.7,47.73 34.94,47.97 35,47.97 36.21,49.18 36.21,51.6 36.09,51.72 36.09,52.23 v2(36.54,52.68)
  BOTTOM w0.127: Q7602.1 31.73,42.33 R7612.1 v1(31.73,44.4) 31.73,44.42 34.1,46.79 34.61,46.79 v2(34.66,46.84) ; v2(36.54,52.68) 36.96,53.1 GPU1.F8
GPIO10_FBVREF: length 112.6
  TOP w0.127: R7610.1 38.59,51.35 39.13,50.8 39.13,50.35 v2(39.02,50.24)
  L3 w0.127: v2(7.97,83.75) 7.91,83.8 7.91,89.79 10.23,92.1 10.23,92.79 12.61,95.18 46.52,95.18 47.16,94.54 v2(47.16,94.16) 47.54,93.78 47.54,93.53 50.97,90.1 50.97,62.79 51.35,62.41 51.35,61.27 50.86,60.79 49.84,60.79 48.99,59.93 46.65,59.93 44.89,58.18 44.89,53.91 43.14,52.15 40.94,52.15 v2(39.02,50.24)
  BOTTOM w0.127: v2(7.97,83.75) 7.74,83.52 Q7901.G ; Q7801.G 51.43,92.94 50.78,93.59 49.97,93.59 49.44,94.12 48.28,94.12 v1(48.01,94.39) 47.46,94.39 47.23,94.16 v2(47.16,94.16) ; v2(39.02,50.24) 39.03,50.24 39.03,50.29 39.39,50.65 GPU1.C5
GPU_CLKREQ#: length 34.2
  BOTTOM w0.127: R7305.2 9.4,33.03 Q7301.S 9.43,33.08 9.68,33.33 R7303.1 v1(9.68,36.38) 9.68,40.58 9.35,40.91 9.35,45.21 11.49,47.34 16.63,47.34 17.15,46.83 20.93,46.83 20.96,46.85 21.19,46.85 21.58,47.24 21.58,50.73 21.95,51.11 22.41,51.11 GPU1.AC6
GPU_EVENT#: length 52.1
  L3 w0.127: v2(2.4,49.76) 4.21,49.76 5.72,48.25 6.46,48.25 8.25,46.46 8.25,45.72 10.15,43.82 10.15,40.99 12.58,38.56 33.72,38.56 34.04,38.24 41.18,38.24 v2(41.95,39.02)
  BOTTOM w0.127: v2(2.4,49.76) 2.4,50.13 2.35,50.17 GPU3.F1 ; v1(41.34,38.94) 41.87,38.94 v2(41.95,39.02) 41.95,39.14 41.51,39.59 R7644.1 R7648.1 40.62,40.58 41.06,41.02 Q7606.D
GPU_EVENT_GPU#: length 14.4
  TOP w0.127: v2(42.26,50.12) 42.22,50.16 40.93,50.16 R7649.1
  BOTTOM w0.127: GPU1.A4 41.1,49.9 41.81,49.9 42.02,50.12 v2(42.26,50.12) 42.26,50.03 42.28,50.01 42.28,48.48 41.87,48.07 41.87,44.53 42.05,44.35 Q7606.S 42.05,43.06 43.25,41.86 v1(43.25,41.38) 43.25,40.85 42.4,40 R7644.2
GPU_I2CA_SCL: length 4.9
  BOTTOM w0.089: RN301.1 43.99,52.51 43.6,52.12 43.55,52.12 v1(43.45,52.02) 43.37,52.02 43.29,51.94 40.56,51.94 GPU1.B7
GPU_I2CA_SDA: length 4.3
  BOTTOM w0.089: GPU1.A7 42.79,52.3 43.47,52.99 43.47,53.11 v1(43.6,53.24) 43.68,53.16 RN301.2
GPU_NC_F11: length 1.2
  TOP w0.254: TP601.1 37.8,54.8 v2(37.42,55.19)
  BOTTOM w0.254: GPU1.F11 36.98,55.62 v2(37.42,55.19)
GPU_PEX_RST#: length 27
  BOTTOM w0.127: 24.4,44.3 24.4,45.01 23.26,46.16 23.26,51.46 23.16,51.56 23.16,51.65 22.8,52 GPU1.AC7 ; 24.4,44.3 24.4,42.68 24.83,42.25 24.83,41.08 24.17,40.41 23.12,40.41 R7313.2 22.47,39.77 v1(22.47,38.87) ; 24.4,44.3 24.44,44.34 26.41,44.34 26.86,43.88 26.86,43.48 R7308.1 R7613.1 28.31,43.73 R7312.2 28.73,44.17 29.68,44.17 30.27,43.58 30.27,42.73 30.55,42.45 30.55,41.63 30.32,41.41 Q7602.5
GPU_PEX_RST_D#: length 3.9
  BOTTOM w0.127: D7301.3 25.7,43.97 v1(26.25,43.97) 26.56,43.67 26.56,42.89 R7308.2
GPU_PEX_RST_HOLD: length 3.6
  BOTTOM w0.127: v1(25.19,38.89) 24.87,39.21 R7630.2 R7631.2 26,40.15 D7301.1
GPU_PEX_RST_HOLD_GPU#: length 28.9
  L3 w0.127: v2(41.24,43.51) 40,43.51 39.48,44.03 36.29,44.03 35,45.33 32.74,45.33 30.43,43.02 26.24,43.02 v2(25.67,42.45)
  BOTTOM w0.127: GPU1.C4 39.78,49.42 39.78,45.35 40.6,44.53 40.6,44.15 v2(41.24,43.51) ; v2(25.67,42.45) 25.14,41.91 25.14,40.95 24.02,39.83 R7630.1 23.98,38.95 v1(23.89,38.87)
GPU_PLL_VDD: length 16.8
  TOP w0.508: v2(32.45,51.92) 32.48,51.9 C7605.1 33.23,51.04 v1(33.29,50.98)
  L6 w0.508: v2(36.11,41.25) 36.11,43.26 35.72,43.65 35.72,44.84 34.03,46.53 34.03,50.85 32.96,51.92 v2(32.45,51.92)
  BOTTOM w0.356: GPU1.L6 32.78,51.59 v2(32.45,51.92)
  BOTTOM w0.508: v2(36.11,41.25) 36.08,41.23 L7601.2 35.22,42.03 C7606.1
GPU_ROM_SCLK: length 8.8
  TOP w0.089: v2(43,56.16) 43,54.96 42.71,54.66 42.12,54.66 R7620.2 41.47,55.29 R7621.1
  BOTTOM w0.089: v1(43.4,56.72) 43.4,56.56 v2(43,56.16) 43,56.09 42.8,55.88 40.71,55.88 40.49,56.1 40.05,56.1 39.7,56.46 GPU1.C12
GPU_ROM_SI: length 12.2
  TOP w0.089: R7622.1 R7624.1 41.34,58.77 R7606.1 R7616.1 R7635.2 42.8,57.88 43.38,57.3 v2(43.41,57.3)
  BOTTOM w0.089: GPU1.B12 40.46,56.46 40.8,56.12 42.19,56.12 43.36,57.3 v2(43.41,57.3) 43.41,58.46 43.65,58.7 R7637.1 44.25,59.2 v1(44.67,59.62)
GPU_ROM_SO: length 3.5
  TOP w0.089: R7618.2 41.42,56.18 v2(41.42,56.85) 41.42,57.79 v1(41.37,57.84) 41.27,57.94 41.27,57.95 R7632.1
  BOTTOM w0.089: GPU1.A12 41,56.46 41.39,56.85 v2(41.42,56.85)
I2CB_SCL: length 6.4
  TOP w0.089: RN7605.3 41.98,51.54 v1(42.38,51.94) 42.76,52.33 v2(42.76,52.96)
  BOTTOM w0.089: GPU1.C9 39.69,53.98 40.05,53.62 40.51,53.62 40.75,53.38 42.25,53.38 42.5,53.13 42.59,53.13 v2(42.76,52.96)
I2CB_SDA: length 4.8
  TOP w0.089: v2(42.1,52.94) 42.1,52.4 41.9,52.2 RN7605.4
  BOTTOM w0.089: GPU1.C8 39.69,53.14 40.17,52.66 41.15,52.66 41.28,52.53 41.69,52.53 v2(42.1,52.94)
I2CC_SCL: length 2.7
  TOP w0.089: RN7604.4 42.41,54.2 42.67,53.94 v2(42.67,53.87)
  BOTTOM w0.089: v2(42.67,53.87) 42.47,53.87 42.36,53.98 GPU1.A9
I2CC_SDA: length 5
  TOP w0.089: v2(43.3,53.76) 43.01,53.47 42.32,53.47 42.23,53.55 RN7604.3
  BOTTOM w0.089: GPU1.B9 40.45,53.98 40.84,53.6 42.34,53.6 42.5,53.44 42.98,53.44 v2(43.3,53.76)
N12P_JTAG_TCK: length 6.3
  BOTTOM w0.102: GPU1.AE5 20.86,50.31 20.86,49.77 20.52,49.43 17.31,49.43 17.21,49.33 RN7602.3
N12P_JTAG_TDI: length 6.1
  BOTTOM w0.102: TP7605.1 16.14,50.9 16.45,50.6 17.52,50.6 18.07,51.16 19.74,51.16 19.94,51.36 19.94,51.53 20.26,51.84 20.69,51.84 21.04,51.5 GPU1.AE6
N12P_JTAG_TDO: length 6.2
  BOTTOM w0.102: TP7601.1 15.31,50.7 16.06,50.7 16.39,50.37 17.61,50.37 18.17,50.93 19.84,50.93 20.4,51.49 GPU1.AF6
N12P_JTAG_TMS: length 8.8
  BOTTOM w0.102: GPU1.AD6 21.58,51.08 20.31,51.08 19.93,50.7 18.26,50.7 17.71,50.14 16.33,50.14 16,50.47 13.91,50.47 TP7602.1
N12P_JTAG_TRST: length 8.5
  BOTTOM w0.102: 15.67,48.67 RN7602.4 ; 15.67,48.67 15.21,48.22 13.45,48.22 v1(13.12,48.54) ; 15.67,48.67 15.58,48.67 15.3,48.96 15.3,49.58 15.52,49.8 GPU1.AG4
N12P_XTAL_OUTBUFF: length 3.1
  TOP w0.102: v2(38.99,55.18) 39.09,55.29 R7602.1 ; v2(38.99,55.18) 38.99,55.21 v1(38.6,55.6) ; v2(38.99,55.18) 38.99,54.52 R7617.2
  BOTTOM w0.102: v2(38.99,55.18) 39.39,54.78 GPU1.C10
OVER_CURRENT_P8#: length 45.6
  L3 w0.102: v2(8.63,54.89) 8.65,54.87 8.69,54.87 10.22,53.33 13.19,53.33 15.66,50.86 15.66,48.43 16.23,47.86 18.61,45.48 18.61,44.25 21.32,41.55 25.88,41.55 26.58,42.24 30.53,42.24 31.21,42.93 37.84,42.93 v2(39.18,41.58)
  BOTTOM w0.102: v2(8.63,54.89) 7.46,54.89 7.15,55.2 GPU3.C9 ; v2(39.18,41.58) 39.18,40.19 38.98,39.99 D7602.K 38.39,39.73 39.1,39.02 v1(39.41,39.02)
OVERT#: length 27.3
  L3 w0.127: v2(45.94,51.36) 45.94,51.3 39.69,45.05 36.11,45.05 35.27,45.89 34.74,45.89 32.58,45.89 31.48,44.78 30.14,44.78 v2(29.07,43.72)
  BOTTOM w0.127: R7656.1 45.86,51.39 45.89,51.36 v2(45.94,51.36) 46.07,51.49 v1(46.52,51.49) ; Q7602.4 28.67,40.76 R7645.2 C7609.1 28.3,42.01 R7613.2 28.31,42.09 29.07,42.85 v2(29.07,43.72)
OVERT_GPU#: length 3.8
  BOTTOM w0.127: 43.4,50.83 v1(43.4,50.8) ; 43.4,50.83 43.5,50.83 44.06,51.39 R7656.2 ; 43.4,50.83 43.17,50.83 42.5,51.5 GPU1.A6
P2800_VGA_DXN: length 1.2
  TOP w0.102: v2(38.18,56.03) 38.18,56.08 TP7603.1
  BOTTOM w0.102: v2(38.18,56.03) 37.8,56.41 TP7603.1
P2800_VGA_DXP: length 1.3
  TOP w0.102: v2(37.39,56) 37.02,55.63 TP7604.1
  BOTTOM w0.102: GPU1.F12 37,56.46 37.39,56.07 v2(37.39,56)
P_H_S#: length 2.4
  BOTTOM w0.102: v1(31.82,38.51) 31.82,38.6 31.85,38.64 R7653.1 31.85,39.79 31.45,40.19 Q7602.3
PEX_TERMP: length 3.6
  TOP w0.102: v2(19.91,65.82) 19.38,65.29 R7301.1 19.13,65.29 18.71,64.87 v1(18.41,64.87)
  BOTTOM w0.102: v2(19.91,65.82) 20.01,65.92 20.01,67.08 20.12,67.2 GPU1.AF25
PEXTSTCLK_OUT: length 2.4
  TOP w0.089: v2(20,64.29) 20.14,64.15 R7307.1 19.5,63.6 v1(19.22,63.33)
  BOTTOM w0.089: v2(20,64.29) 20.01,64.3 20.01,64.32 20.39,64.7 GPU1.AF22
PEXTSTCLK_OUT#: length 2.4
  TOP w0.089: v1(20.61,62.69) 21.03,63.11 R7307.2 21.03,64.07 v2(20.81,64.3)
  BOTTOM w0.089: GPU1.AE22 21.2,64.7 20.82,64.32 20.82,64.31 v2(20.81,64.3)
PLT_RST#: length 21.6
  L3 w0.102: v2(18.81,42.79) 18.29,43.3 18.29,45.37 15.36,48.3 15.36,50.74 13.07,53.03 10.1,53.03 8.87,54.26 v2(8.58,54.26)
  BOTTOM w0.102: v2(8.58,54.26) 8.55,54.28 GPU3.D10 ; U7301.2 19.26,41.9 18.81,42.35 v2(18.81,42.79) 18.68,42.91 v1(18.68,44.02)
PURE_HW_SHUTDOWN#: length 2.8
  BOTTOM w0.102: R7653.2 29.73,39.42 TP7607.1 29.33,39.02 C7610.1
PWR_1D05V_EN: length 1
  BOTTOM w0.254: v1(2.28,73.08) 2.47,72.89 PC8302.1
PWR_1D05V_FB: length 6.2
  BOTTOM w0.305: PU8301.6 4.63,76.34 4.18,76.79
  BOTTOM w0.508: PR8303.2 PC8305.2 PR8302.1 4.1,76.86 4.18,76.79 ; PR8303.2 2.33,77.17 PC8312.1 ; PR8303.2 2.29,77.88 v1(1.39,77.88)
PWR_1D05V_FB_R: length 2
  BOTTOM w0.102: PC8312.2 2.26,75.28 PR8313.1 v1(1.36,74.6)
PWR_1D05V_PGOOD: length 3.7
  TOP w0.127: v2(4.66,71.58) 4.49,71.4 4.05,71.4 v1(4,71.45) 3.98,71.48 PR8320.1 PR8304.2
  BOTTOM w0.127: PU8301.4 5.13,72.05 v2(4.66,71.58)
PWR_1D05V_PHASE: length 1.1
  BOTTOM w0.254: v1(8.04,69.17) 6.92,69.17
PWR_1D05V_PVDD:
  vias: v1(7.25,77.57)
PWR_1D05V_SVIN: length 3.6
  BOTTOM w0.305: PR8301.2 5.63,76.95 PU8301.8
  BOTTOM w0.508: PR8301.2 5.02,77.56 v1(5.02,77.87) 4.99,77.89 4.99,78.88 PC8301.1
PWR_1D35V_BOOT: length 3.3
  BOTTOM w0.254: v1(52.19,15.68) 51.32,16.54 PR8324.1 51.08,16.58 PU8302.1
PWR_1D35V_BOOT_R: length 2.3
  BOTTOM w0.508: PR8324.2 52.7,16.82 52.95,17.07 v1(52.95,18.01) 52.1,18.01 PC8319.1
PWR_1D35V_BYP: length 3
  BOTTOM w0.254: PR8325.1 PC8318.1 44.69,16.58 PU8302.15
PWR_1D35V_EN: length 5.8
  BOTTOM w0.127: v1(43.96,10.26) 44.16,10.26 44.69,10.8 44.69,11.27 PR8322.2 PC8316.1 46.75,14.19 PU8302.11
PWR_1D35V_IMAX: length 3.9
  BOTTOM w0.254: PR8323.2 45.58,13.91 45.58,15.17 46.09,15.68 PU8302.13
PWR_1D35V_LDO_P5: length 3.4
  BOTTOM w0.254: v1(44.72,19.74) 44.72,18.9 PC8317.1 45.78,18.6 46.78,17.59
PWR_1D35V_PGOOD: length 6.6
  BOTTOM w0.127: PU8302.9 47.72,13.69 47.27,13.24 ; v1(45.18,10.21) 45.18,11.55 45.89,12.26 PR8311.2 PR8321.2 47.27,12.81 47.27,13.24 ; PU8302.10 47.27,13.24
PWR_1D35V_PHASE: length 6.2
  TOP w0.254: v1(49.57,14.13) 49.62,14.07 v2(49.62,13.57)
  L6 w0.508: v2(49.62,13.57) 50.46,14.41 v2(50.46,17.88)
  BOTTOM w0.254: PU8302.6 49.07,14.11 v2(49.62,13.57)
PWR_1D35V_VFB: length 4
  BOTTOM w0.254: PU8302.14 45.73,16.13 45.28,15.68 PR8326.1
  BOTTOM w0.508: PR8326.1 PC8308.2 PR8327.2
PWR_1D35V_VFB1: length 18.9
  TOP w0.508: v1(43.93,30.18) 43.93,29.65 v2(43.98,29.59)
  L3 w0.508: v2(43.98,29.59) 43.98,29.16 44.67,28.48 44.67,16.34 v2(43.14,14.81)
  BOTTOM w0.254: 44.01,28.86 PG8313.2
  BOTTOM w0.508: PR8327.1 PC8308.1 43.17,14.79 v2(43.14,14.81) ; v2(43.98,29.59) 44.01,29.57 44.01,28.86
PWR_DCBATOUT_1D35V:
  vias: v1(51.78,13.36)
PWR_LEVEL: length 29.4
  BOTTOM w0.127: GPU1.D7 38.6,52 38.96,51.65 38.96,51.44 39.39,51.01 39.55,51.01 39.84,50.71 39.84,50.5 40.19,50.16 41.24,50.16 41.7,50.16 42.08,50.54 42.43,50.54 42.67,50.29 42.67,48.51 42.15,47.99 42.15,44.61 43.78,42.98 43.78,40.54 v1(43.3,40.06) 43.3,40.03 42.93,39.66 42.93,39.61 42.4,39.07 42.4,38.83 41.8,38.24 38.69,38.24 37.73,39.2 37.73,40.38 D7602.A D7601.A 36.77,41.2 36.97,41.41 37.3,41.41 37.7,41.8 R7605.2
PWR_VGA_CORE_BOOT1: length 2.4
  BOTTOM w0.203: 32.48,8.03 31.8,7.35 PU8201.1
  BOTTOM w0.508: PR8210.1 32.52,8.08 32.48,8.03
PWR_VGA_CORE_BOOT1_1: length 1.3
  BOTTOM w0.508: PR8210.2 PC8211.1
PWR_VGA_CORE_BOOT2: length 2.4
  BOTTOM w0.203: 27.57,7.8 28.02,7.35 PU8201.15
  BOTTOM w0.508: PR8211.1 26.59,8.79 27.57,7.8
PWR_VGA_CORE_BOOT2_1: length 2.4
  BOTTOM w0.508: v1(24.04,10.11) 24.25,10.11 24.25,10.12 25.05,10.12 PC8216.1 PR8211.2
PWR_VGA_CORE_EN: length 9
  BOTTOM w0.254: PU8201.3 33.07,6.55 PC8225.2 34.33,6.95 PR8256.2 PR8260.2 35.23,6.95 35.75,7.47 36.17,7.47 36.46,7.17 v1(36.62,7.17) 37.06,7.17 37.46,7.57 37.46,8.77 37.05,9.17 PQ8305.2
PWR_VGA_CORE_EN#: length 5.2
  TOP w0.127: v1(39.56,8.11) 38.95,7.5 v2(38.95,7.37)
  BOTTOM w0.127: 38.39,9.17 39.49,9.17 PR8315.1 39.18,8.52 38.39,8.52 38.39,8.03 38.95,7.47 v2(38.95,7.37)
PWR_VGA_CORE_LGATE1: length 14.8
  TOP w0.254: v3(30.47,9.22) 30.47,9.88 v1(30.5,9.91)
  TOP w0.762: PU8204.8 v3(31.78,13.26)
  L6 w1.016: v3(31.78,18.85) v3(31.78,13.26) 31.78,11.94 30.47,10.63 v3(30.47,9.22)
  BOTTOM w0.203: PU8201.19 30.24,8.71 30.47,8.94 v3(30.47,9.22)
  BOTTOM w0.508: PR8224.1 31.02,9.22 v3(30.47,9.22)
  BOTTOM w0.762: PU8202.8 v3(31.78,18.85)
